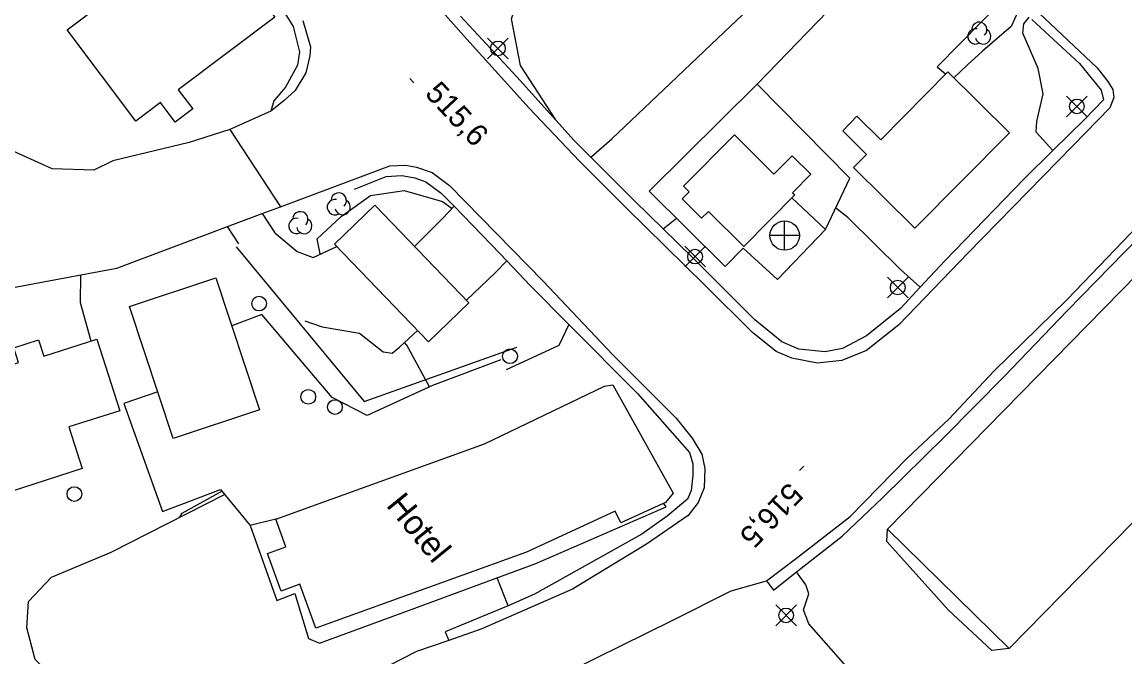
# Model space of a CAD drawing. Extents: x 347312 to 350503, y 6073086 to 6076432.
# Drawn here: x 348327.1 to 348477.3, y 6074553.2 to 6074639.7 of the extents above; entities that cross this region are included whole.
import ezdxf

# ---------------------------------------------------------------- set-up
doc = ezdxf.new("R2010")
doc.units = 0
for name, color, linetype in [('Level 16', 7, 'Continuous'), ('Level 19', 7, 'Continuous'), ('Level 2', 7, 'Continuous'), ('Level 21', 7, 'Continuous'), ('Level 22', 7, 'Continuous'), ('Level 3', 7, 'Continuous'), ('Level 31', 7, 'Continuous'), ('Level 36', 7, 'Continuous'), ('Level 37', 7, 'Continuous'), ('Level 44', 7, 'Continuous')]:
    doc.layers.add(name, color=color, linetype=linetype)

msp = doc.modelspace()

# ---------------------------------------------------------------- linework, layer by layer
at = {"layer": 'Level 16'}
for p, q in [((348430.97, 6074608.62), (348430.97, 6074612.62)), ((348432.97, 6074610.62), (348428.97, 6074610.62))]:
    msp.add_line(p, q, dxfattribs=at)
msp.add_circle((348430.98, 6074610.61), 2, dxfattribs=at)
at = {"layer": 'Level 19'}
for points in [[(348404.56, 6074621.32), (348407.44, 6074623.79), (348414.52, 6074630.5), (348421.87, 6074637.51), (348431.81, 6074646.98), (348441.45, 6074656.19), (348444.44, 6074659.43)], [(348463, 6074641.61), (348461.84, 6074639.11), (348457.94, 6074635.75), (348455.89, 6074633.88), (348454.03, 6074632.13)], [(348467.54, 6074622.22), (348465.25, 6074624.71), (348465.33, 6074626.15), (348466.19, 6074629.91), (348465.54, 6074633.4), (348463.44, 6074638.19), (348463.59, 6074639.46), (348464.29, 6074640.4)], [(348438.9, 6074624.91), (348440.83, 6074626.91), (348444.09, 6074623.67), (348453.23, 6074632.91), (348461.6, 6074624.63), (348448.71, 6074611.61), (348440.35, 6074619.89), (348442.11, 6074621.67), (348438.9, 6074624.91)], [(348359.78, 6074613.61), (348361.51, 6074611), (348364.55, 6074608.43), (348366.73, 6074607.62), (348369.93, 6074609.13)], [(348380.54, 6074609.14), (348384.36, 6074612.92), (348385.92, 6074614.6)], [(348449.45, 6074603.57), (348446.78, 6074605.97), (348439.57, 6074613.08), (348437.93, 6074614.36)], [(348414.4, 6074611.54), (348416.25, 6074612.99)], [(348356.61, 6074609.47), (348355.07, 6074611.84)], [(348387.61, 6074601.8), (348391.55, 6074605.53), (348393.13, 6074607.15)], [(348336.49, 6074596.24), (348335, 6074601.44), (348335.05, 6074605.26)], [(348365.57, 6074598.99), (348367.95, 6074598.2), (348373.02, 6074597.33), (348376.27, 6074594.79), (348377.5, 6074594.57), (348378.51, 6074595.42), (348380.96, 6074597.68)], [(348401.57, 6074598.5), (348400.2, 6074595.64), (348393.01, 6074592.33)], [(348369.97, 6074541.92), (348368.89, 6074542.25), (348360.59, 6074542.06), (348355.46, 6074541.73), (348346.42, 6074543.43), (348339.22, 6074546.53), (348331.69, 6074550.03), (348328.84, 6074552.82), (348327.72, 6074557.14), (348327.94, 6074560.76), (348331.06, 6074564.07), (348339.18, 6074567.47), (348354.64, 6074575.35)], [(348461.58, 6074554.33), (348459.22, 6074554.07), (348453.25, 6074559.61), (348444.89, 6074568.94), (348444.97, 6074570.61)], [(348393.3, 6074560.16), (348391.82, 6074563.99)], [(348408.93, 6074496.8), (348412.13, 6074500.55), (348419.03, 6074507.64), (348425.42, 6074514.16), (348433.56, 6074522.37), (348436.56, 6074527.71), (348440.03, 6074534.65), (348442.69, 6074538.41), (348446.07, 6074541.03), (348446.38, 6074542.74), (348445.02, 6074545.01), (348438.99, 6074552.33), (348434.27, 6074557.72), (348433.53, 6074559.61), (348434.25, 6074561.81), (348433.86, 6074563.01), (348432.6, 6074564.78)]]:
    msp.add_lwpolyline(points, dxfattribs=at)
at = {"layer": 'Level 2'}
for points in [[(348399.78, 6074626.37), (348395, 6074633.77), (348393.74, 6074640.14), (348394.83, 6074643.59), (348397.22, 6074647.38), (348406.96, 6074657.73), (348414.52, 6074668.36), (348419.17, 6074674.92), (348419.4, 6074676.62), (348418.93, 6074677.68)], [(348367.72, 6074608.09), (348367.7, 6074608.11), (348367.29, 6074610.16), (348370.55, 6074613.22), (348374.52, 6074616.07), (348379.12, 6074616.75), (348384.35, 6074615.25), (348385.65, 6074614.31)], [(348382.59, 6074589.99), (348379.51, 6074595.7), (348379.19, 6074596.04)], [(348348.54, 6074572.24), (348348.89, 6074572.79), (348354.28, 6074575.8)]]:
    msp.add_lwpolyline(points, dxfattribs=at)
at = {"layer": 'Level 21'}
for points in [[(348464.08, 6074642.41), (348473.55, 6074633.46), (348475, 6074631.63), (348475.68, 6074630.54), (348475.84, 6074629.45), (348475.3, 6074628.01), (348470.3, 6074622.89), (348455.98, 6074608.26), (348446.55, 6074598.43), (348442.14, 6074594.95), (348438.78, 6074593.57), (348435.46, 6074593.21), (348431.94, 6074593.91), (348429.83, 6074594.81), (348426.6, 6074597.42), (348420.11, 6074603.85), (348409.36, 6074614.41), (348403.02, 6074620.75), (348396.16, 6074627.99), (348387.28, 6074637.83), (348382.68, 6074643.07)], [(348365.3, 6074639.93), (348366.37, 6074636.32), (348366.26, 6074635.1), (348365.72, 6074632.78), (348364.27, 6074630.38), (348362.71, 6074629), (348360.98, 6074627.57), (348355.35, 6074625.06), (348362.29, 6074614.55), (348372.07, 6074618.21), (348377.16, 6074620.12), (348379.33, 6074620.21), (348380.82, 6074619.95), (348382.93, 6074619.23), (348385.3, 6074617.46), (348398.06, 6074604.41), (348407.58, 6074594.34), (348416.19, 6074585.73), (348418.38, 6074583.01), (348419.68, 6074580.82), (348420.09, 6074578.88), (348420.03, 6074576.24), (348419.2, 6074574.25), (348417.82, 6074572.48), (348412.14, 6074568.54), (348402.07, 6074562.44), (348389.72, 6074557.01), (348385.21, 6074555.45), (348380.82, 6074553.94), (348377.08, 6074552.01)], [(348355.35, 6074625.06), (348349.83, 6074623.31), (348339.45, 6074620.82), (348336.86, 6074619.53), (348331.15, 6074619.73), (348322.5, 6074623.62), (348313.34, 6074621.1), (348292.78, 6074614.64), (348295.6, 6074601.54), (348297.29, 6074595.91), (348312.03, 6074600.37), (348314.14, 6074601.34), (348317.36, 6074601.94), (348335.05, 6074605.26), (348339.96, 6074606.18), (348355.07, 6074611.84), (348359.78, 6074613.61), (348362.29, 6074614.55)], [(348390.25, 6074513.73), (348388.2, 6074517.18), (348385.35, 6074526.28), (348382.45, 6074535.8), (348382.52, 6074537.08), (348383.64, 6074539.7), (348385.22, 6074541.25), (348385.58, 6074541.63), (348392.16, 6074543.59), (348392.98, 6074546.41), (348393.71, 6074547.25), (348401.83, 6074551.34), (348415.65, 6074558.17), (348423.68, 6074562.18), (348428.49, 6074563.55), (348432.61, 6074566.64), (348439.92, 6074572.33), (348447.67, 6074580.29), (348453.39, 6074585.63), (348459.49, 6074592.13), (348469.49, 6074601.91), (348481.4, 6074614.36)]]:
    msp.add_lwpolyline(points, dxfattribs=at)
at = {"layer": 'Level 22'}
for points in [[(348308.44, 6074675.94), (348309.03, 6074674.47), (348312.69, 6074676.54), (348322.89, 6074681.92), (348330.76, 6074686.52), (348331.99, 6074686.57), (348332.48, 6074686.08), (348334.62, 6074682.7), (348340.12, 6074673.86), (348345.26, 6074665.54), (348351.94, 6074655.82), (348362.39, 6074641.67), (348364, 6074639.11), (348364.87, 6074635.64), (348364.58, 6074633.83), (348362.96, 6074630.83), (348361.36, 6074628.97), (348360.98, 6074627.57)], [(348464.65, 6074640.07), (348471.16, 6074634.05), (348474.1, 6074630.43), (348474.44, 6074629.11), (348471.87, 6074626.5), (348467.54, 6074622.22), (348463.61, 6074618.33), (348452.79, 6074607.18), (348449.45, 6074603.57), (348446.77, 6074600.67), (348442.13, 6074596.93), (348438.87, 6074595.24), (348436.48, 6074594.76), (348432.93, 6074595.13), (348430.59, 6074596.13), (348426.9, 6074599.12), (348418.37, 6074607.65), (348414.4, 6074611.54), (348410.54, 6074615.32), (348404.56, 6074621.32), (348402.29, 6074623.59), (348394.46, 6074632.27), (348386.82, 6074640.52)], [(348372.38, 6074616.96), (348376.67, 6074618.66), (348378.81, 6074618.79), (348380.58, 6074618.47), (348382.08, 6074617.92), (348384.19, 6074616.38), (348385.92, 6074614.6), (348392.19, 6074608.13), (348393.13, 6074607.15), (348396.34, 6074603.78), (348401.57, 6074598.5), (348410.93, 6074589.08), (348417.99, 6074581.07), (348418.47, 6074579.49), (348418.46, 6074577.96), (348418.24, 6074575.88), (348417.73, 6074574.68), (348414.98, 6074572.37), (348411.53, 6074569.92), (348396.89, 6074561.73), (348393.3, 6074560.16), (348384.73, 6074556.61), (348385.21, 6074555.45)], [(348428.49, 6074563.55), (348429.45, 6074562.31), (348432.6, 6074564.78), (348438.83, 6074569.66), (348442.48, 6074573.14), (348444.29, 6074574.86), (348452.86, 6074583.28), (348460.87, 6074591.39), (348469.48, 6074600.38), (348479.29, 6074610.38), (348485.96, 6074617.2), (348486.64, 6074617.47), (348487.88, 6074616.61), (348495.41, 6074609.18), (348505.44, 6074599.74), (348509.38, 6074595.9), (348518.32, 6074587.24), (348526.75, 6074578.9), (348531.89, 6074573.89), (348532.5, 6074572.8), (348532.06, 6074572.06), (348530.81, 6074570.77), (348531.81, 6074569.67)]]:
    msp.add_lwpolyline(points, dxfattribs=at)
at = {"layer": 'Level 3'}
for p, q in [((348379.88, 6074632), (348380.43, 6074631.41)), ((348433.57, 6074579.2), (348433.02, 6074578.62))]:
    msp.add_line(p, q, dxfattribs=at)
at = {"layer": 'Level 31'}
for points in [[(348333.2, 6074638.66), (348352.11, 6074652.9), (348361.52, 6074640.4), (348348.35, 6074630.48), (348350.31, 6074627.88), (348347.91, 6074626.07), (348345.91, 6074628.73), (348342.57, 6074626.21), (348333.2, 6074638.66)], [(348432.35, 6074616.15), (348425.4, 6074609.13), (348420.58, 6074613.9), (348419.65, 6074612.97), (348416.99, 6074615.6), (348417.95, 6074616.57), (348417.18, 6074617.33), (348424.13, 6074624.34), (348429.52, 6074618.99), (348432, 6074621.5), (348434.55, 6074618.97), (348432.05, 6074616.45), (348432.35, 6074616.15)], [(348382.45, 6074596.13), (348369.63, 6074609.44), (348375.14, 6074614.75), (348387.96, 6074601.44), (348382.45, 6074596.13)], [(348444.97, 6074570.61), (348488.13, 6074614.63), (348504.85, 6074598.24), (348494.37, 6074587.55), (348497.21, 6074584.77), (348490.83, 6074578.26), (348487.88, 6074581.15), (348461.58, 6074554.33), (348444.97, 6074570.61)], [(348347.66, 6074582.97), (348341.71, 6074600.95), (348353.48, 6074604.84), (348359.42, 6074586.86), (348347.66, 6074582.97)], [(348327, 6074576.21), (348309.85, 6074570.74), (348304.96, 6074586.08), (348319.72, 6074590.79), (348319.62, 6074591.1), (348326.59, 6074593.32), (348325.95, 6074595.33), (348329.31, 6074596.4), (348330.02, 6074594.17), (348337.26, 6074596.48), (348340.37, 6074586.74), (348333.45, 6074584.53), (348335.26, 6074578.85), (348327, 6074576.21)], [(348407.57, 6074590.26), (348415.77, 6074575.5), (348414.72, 6074574.25), (348408.67, 6074571.47), (348407.89, 6074573.04), (348395.79, 6074567.47), (348367.1, 6074557.09), (348364.93, 6074563.1), (348362.35, 6074562.17), (348360.5, 6074567.28), (348363.01, 6074568.19), (348361.65, 6074571.95), (348390.08, 6074582.23), (348406.44, 6074590.1), (348407.57, 6074590.26)]]:
    msp.add_lwpolyline(points, dxfattribs=at)
at = {"layer": 'Level 36'}
for p, q in [((348390.5, 6074634.72), (348393.32, 6074637.54)), ((348390.5, 6074637.54), (348393.32, 6074634.72)), ((348469.39, 6074626.81), (348472.21, 6074629.63)), ((348469.39, 6074629.63), (348472.21, 6074626.81)), ((348417.36, 6074606.34), (348420.18, 6074609.16)), ((348417.36, 6074609.16), (348420.18, 6074606.34)), ((348444.97, 6074602.13), (348447.79, 6074604.95)), ((348444.97, 6074604.95), (348447.79, 6074602.13)), ((348429.77, 6074557.45), (348432.59, 6074560.27)), ((348429.77, 6074560.27), (348432.59, 6074557.45))]:
    msp.add_line(p, q, dxfattribs=at)
for centre in [(348391.91, 6074636.13), (348470.8, 6074628.22), (348418.77, 6074607.75), (348446.38, 6074603.54), (348359.36, 6074601.34), (348393.55, 6074594.16), (348366.06, 6074588.64), (348369.69, 6074587.25), (348334.19, 6074575.39), (348431.18, 6074558.86)]:
    msp.add_circle(centre, 1, dxfattribs=at)
at = {"layer": 'Level 37'}
for points in [[(348427.25, 6074631.24), (348449.25, 6074654.06), (348460.9, 6074642.94), (348451.74, 6074633.63), (348452.92, 6074632.6)], [(348436.53, 6074611.43), (348439.87, 6074618.43), (348427.25, 6074631.24), (348412.53, 6074616.67), (348422.87, 6074606.42), (348425.31, 6074608.92), (348429.99, 6074604.65), (348436.53, 6074611.43), (348431.95, 6074615.74)], [(348356.24, 6074609.09), (348373.69, 6074587.99), (348394.47, 6074595.4)], [(348392.31, 6074593.66), (348383.01, 6074590.18), (348374.07, 6074586.09), (348369.31, 6074588.56), (348359.72, 6074599.88), (348355.63, 6074598.33)], [(348345.57, 6074589.3), (348340.94, 6074587.75), (348346.21, 6074572.99), (348354.12, 6074575.99), (348358.16, 6074571.1)], [(348362, 6074572.07), (348358.16, 6074571.1), (348361.78, 6074560.9), (348364.24, 6074561.83), (348366.09, 6074555.71), (348367.6, 6074555.07), (348378.84, 6074559.2), (348397.07, 6074565.94), (348414.81, 6074573.63), (348414.48, 6074574.14)]]:
    msp.add_lwpolyline(points, dxfattribs=at)
at = {"layer": 'Level 44'}
for centre, start, end in [((348457.5, 6074638.66), 314.0633, 179.7519), ((348456.98, 6074637.76), 76.8848, 299.5691), ((348458.03, 6074637.76), 192.2171, 59.6742), ((348369.69, 6074614.49), 76.8848, 299.5691), ((348370.21, 6074615.39), 314.0633, 179.7519), ((348370.74, 6074614.49), 192.2171, 59.6742), ((348364.98, 6074612.82), 314.0633, 179.7519), ((348364.46, 6074611.92), 76.8848, 299.5691), ((348365.51, 6074611.92), 192.2171, 59.6742)]:
    msp.add_arc(centre, 1.05, start, end, dxfattribs=at)

# ---------------------------------------------------------------- texts
at = {"layer": 'Level 3'}
for s, rotation, p in [('515,6', 313.0457, (348381.83, 6074629.86)), ('516,5', 226.3579, (348431.56, 6074577.14))]:
    msp.add_text(s, height=3, rotation=rotation, dxfattribs=at).set_placement(p)
at = {"layer": 'Level 31'}
msp.add_text('Hotel', height=3.33, rotation=309.1656, dxfattribs=at).set_placement((348376.57, 6074573.82))

doc.saveas('drawing.dxf')
